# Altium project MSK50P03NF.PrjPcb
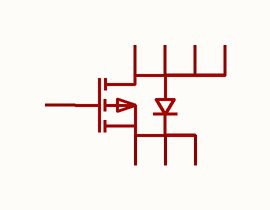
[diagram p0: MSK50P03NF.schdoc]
1 sheet, 1 parts. Net scope: global (net labels, ports and power ports of the same name join across sheets).

## Sheet MSK50P03NF.schdoc
size 127 x 101 mm

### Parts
Q?  msk50p03nf  [DFN-8_L6.0-W5.0-P1.27-LS6.2-BL]  (value not drawn)

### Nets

Not connected (* = marked no-connect by the designer): Q? 1(S) 2(S) 3(S) 4(G) 5(D) 6(D) 7(D) 8(D)

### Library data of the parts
Q? = msk50p03nf: 数量:-;漏源电压(Vdss):30V;连续漏极电流(Id):50A;导通电阻(RDS(on)):9mΩ@10V；18mΩ@4.5V;耗散功率(Pd):3W;阈值电压(Vgs(th)):1.5V;; Manufacturer: MSKSEMI(美森科); AddInBom: yes; ModelId: 45576c36616e4ff29cfec248511b0738; ModelTransform: 204.724,242.1255,0,0,0,0,0,-3.937,0; Drain to Source Voltage: 30V; Current - Continuous Drain(Id): 50A; Pd - Power Dissipation: 3W; Gate Threshold Voltage (Vgs(th)): 1.5V; Gate Charge(Qg): 24nC@10V; Input Capacitance(Ciss): 1.75nF; Reverse Transfer Capacitance (Crss@Vds): 180pF; Type: P沟道; Output Capacitance(Coss): 215pF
